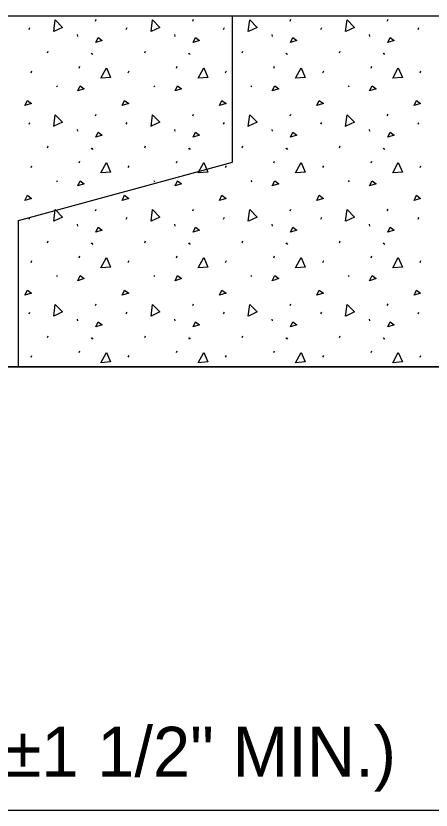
# Model space of a CAD drawing. Extents: x 49991.4 to 50021, y 49987.6 to 50011.4.
# Drawn here: x 50013.228 to 50013.726, y 49990.392 to 49991.345 of the extents above; entities that cross this region are included whole.
import ezdxf

# ---------------------------------------------------------------- set-up
doc = ezdxf.new("R2010")
doc.units = 0
for name, color, linetype in [('Level 1', 7, 'Continuous'), ('Level 2', 7, 'Continuous'), ('Level 3', 7, 'Continuous')]:
    doc.layers.add(name, color=color, linetype=linetype)

msp = doc.modelspace()

# ---------------------------------------------------------------- linework, layer by layer
at = {"layer": 'Level 1'}
for p, q in [((50012.2443, 49991.3452), (50014.4739, 49991.3452)), ((50012.2443, 49991.3452), (50014.4739, 49991.3452)), ((50013.4875, 49991.1697), (50013.4875, 49991.3452)), ((50013.3229, 49991.3389), (50013.3239, 49991.3411)), ((50013.4396, 49991.3389), (50013.4406, 49991.3411)), ((50013.5563, 49991.3389), (50013.5573, 49991.3411)), ((50013.673, 49991.3389), (50013.674, 49991.3411)), ((50013.2433, 49991.3289), (50013.2442, 49991.3311)), ((50013.3599, 49991.3289), (50013.3609, 49991.3311)), ((50013.4766, 49991.3289), (50013.4776, 49991.3311)), ((50013.5933, 49991.3289), (50013.5943, 49991.3311)), ((50013.71, 49991.3289), (50013.711, 49991.3311)), ((50013.3012, 49991.3228), (50013.3014, 49991.3206)), ((50013.4179, 49991.3228), (50013.4181, 49991.3206)), ((50013.5346, 49991.3228), (50013.5348, 49991.3206)), ((50013.6512, 49991.3228), (50013.6515, 49991.3206)), ((50013.2654, 49991.3007), (50013.2664, 49991.3029)), ((50013.3178, 49991.3007), (50013.3188, 49991.2992)), ((50013.3188, 49991.3001), (50013.3197, 49991.2987)), ((50013.3821, 49991.3007), (50013.3831, 49991.3029)), ((50013.4345, 49991.3007), (50013.4355, 49991.2992)), ((50013.4355, 49991.3001), (50013.4364, 49991.2987)), ((50013.4988, 49991.3007), (50013.4998, 49991.3029)), ((50013.5512, 49991.3007), (50013.5522, 49991.2992)), ((50013.5522, 49991.3001), (50013.5531, 49991.2987)), ((50013.6155, 49991.3007), (50013.6165, 49991.3029)), ((50013.6679, 49991.3007), (50013.6688, 49991.2992)), ((50013.6688, 49991.3001), (50013.6698, 49991.2987)), ((50013.2457, 49991.277), (50013.2467, 49991.2792)), ((50013.3034, 49991.2826), (50013.3044, 49991.2848)), ((50013.3624, 49991.277), (50013.3634, 49991.2792)), ((50013.4201, 49991.2826), (50013.4211, 49991.2848)), ((50013.4791, 49991.277), (50013.48, 49991.2792)), ((50013.5368, 49991.2826), (50013.5378, 49991.2848)), ((50013.5958, 49991.277), (50013.5967, 49991.2792)), ((50013.6535, 49991.2826), (50013.6545, 49991.2848)), ((50013.7124, 49991.277), (50013.7134, 49991.2792)), ((50013.2761, 49991.2614), (50013.2771, 49991.26)), ((50013.3928, 49991.2614), (50013.3938, 49991.26)), ((50013.5095, 49991.2614), (50013.5105, 49991.26)), ((50013.6262, 49991.2614), (50013.6272, 49991.26)), ((50013.3229, 49991.2251), (50013.3239, 49991.2273)), ((50013.4396, 49991.2251), (50013.4406, 49991.2273)), ((50013.5563, 49991.2251), (50013.5573, 49991.2273)), ((50013.673, 49991.2251), (50013.674, 49991.2273)), ((50013.2433, 49991.2152), (50013.2442, 49991.2173)), ((50013.3599, 49991.2152), (50013.3609, 49991.2173)), ((50013.4766, 49991.2152), (50013.4776, 49991.2173)), ((50013.5933, 49991.2152), (50013.5943, 49991.2173)), ((50013.71, 49991.2152), (50013.711, 49991.2173)), ((50013.3012, 49991.209), (50013.3014, 49991.2068)), ((50013.4179, 49991.209), (50013.4181, 49991.2068)), ((50013.5346, 49991.209), (50013.5348, 49991.2068)), ((50013.6512, 49991.209), (50013.6515, 49991.2068)), ((50013.2654, 49991.1869), (50013.2664, 49991.1891)), ((50013.3178, 49991.1869), (50013.3188, 49991.1854)), ((50013.3188, 49991.1863), (50013.3197, 49991.1849)), ((50013.3821, 49991.1869), (50013.3831, 49991.1891)), ((50013.4345, 49991.1869), (50013.4355, 49991.1854)), ((50013.4355, 49991.1863), (50013.4364, 49991.1849)), ((50013.4988, 49991.1869), (50013.4998, 49991.1891)), ((50013.5512, 49991.1869), (50013.5522, 49991.1854)), ((50013.5522, 49991.1863), (50013.5531, 49991.1849)), ((50013.6155, 49991.1869), (50013.6165, 49991.1891)), ((50013.6679, 49991.1869), (50013.6688, 49991.1854)), ((50013.6688, 49991.1863), (50013.6698, 49991.1849)), ((50013.2306, 49991.0998), (50013.4875, 49991.1697)), ((50013.2457, 49991.1632), (50013.2467, 49991.1654)), ((50013.3034, 49991.1688), (50013.3044, 49991.171)), ((50013.3624, 49991.1632), (50013.3634, 49991.1654)), ((50013.4201, 49991.1688), (50013.4211, 49991.171)), ((50013.4791, 49991.1632), (50013.48, 49991.1654)), ((50013.5368, 49991.1688), (50013.5378, 49991.171)), ((50013.5958, 49991.1632), (50013.5967, 49991.1654)), ((50013.6535, 49991.1688), (50013.6545, 49991.171)), ((50013.7124, 49991.1632), (50013.7134, 49991.1654)), ((50013.2761, 49991.1477), (50013.2771, 49991.1462)), ((50013.3928, 49991.1477), (50013.3938, 49991.1462)), ((50013.5095, 49991.1477), (50013.5105, 49991.1462)), ((50013.6262, 49991.1477), (50013.6272, 49991.1462)), ((50013.3229, 49991.1114), (50013.3239, 49991.1135)), ((50013.4396, 49991.1114), (50013.4406, 49991.1135)), ((50013.5563, 49991.1114), (50013.5573, 49991.1135)), ((50013.673, 49991.1114), (50013.674, 49991.1135)), ((50013.2306, 49990.9242), (50013.2306, 49991.0998)), ((50013.2433, 49991.1014), (50013.2442, 49991.1036)), ((50013.3599, 49991.1014), (50013.3609, 49991.1036)), ((50013.4766, 49991.1014), (50013.4776, 49991.1036)), ((50013.5933, 49991.1014), (50013.5943, 49991.1036)), ((50013.71, 49991.1014), (50013.711, 49991.1036)), ((50013.3012, 49991.0952), (50013.3014, 49991.0931)), ((50013.4179, 49991.0952), (50013.4181, 49991.0931)), ((50013.5346, 49991.0952), (50013.5348, 49991.0931)), ((50013.6512, 49991.0952), (50013.6515, 49991.0931)), ((50013.2654, 49991.0731), (50013.2664, 49991.0753)), ((50013.3178, 49991.0731), (50013.3188, 49991.0716)), ((50013.3188, 49991.0726), (50013.3197, 49991.0711)), ((50013.3821, 49991.0731), (50013.3831, 49991.0753)), ((50013.4345, 49991.0731), (50013.4355, 49991.0716)), ((50013.4355, 49991.0726), (50013.4364, 49991.0711)), ((50013.4988, 49991.0731), (50013.4998, 49991.0753)), ((50013.5512, 49991.0731), (50013.5522, 49991.0716)), ((50013.5522, 49991.0726), (50013.5531, 49991.0711)), ((50013.6155, 49991.0731), (50013.6165, 49991.0753)), ((50013.6679, 49991.0731), (50013.6688, 49991.0716)), ((50013.6688, 49991.0726), (50013.6698, 49991.0711)), ((50013.2457, 49991.0494), (50013.2467, 49991.0516)), ((50013.3034, 49991.0551), (50013.3044, 49991.0572)), ((50013.3624, 49991.0494), (50013.3634, 49991.0516)), ((50013.4201, 49991.0551), (50013.4211, 49991.0572)), ((50013.4791, 49991.0494), (50013.48, 49991.0516)), ((50013.5368, 49991.0551), (50013.5378, 49991.0572)), ((50013.5958, 49991.0494), (50013.5967, 49991.0516)), ((50013.6535, 49991.0551), (50013.6545, 49991.0572)), ((50013.7124, 49991.0494), (50013.7134, 49991.0516)), ((50013.2761, 49991.0339), (50013.2771, 49991.0324)), ((50013.3928, 49991.0339), (50013.3938, 49991.0324)), ((50013.5095, 49991.0339), (50013.5105, 49991.0324)), ((50013.6262, 49991.0339), (50013.6272, 49991.0324)), ((50013.3229, 49990.9976), (50013.3239, 49990.9998)), ((50013.4396, 49990.9976), (50013.4406, 49990.9998)), ((50013.5563, 49990.9976), (50013.5573, 49990.9998)), ((50013.673, 49990.9976), (50013.674, 49990.9998)), ((50013.2433, 49990.9876), (50013.2442, 49990.9898)), ((50013.3599, 49990.9876), (50013.3609, 49990.9898)), ((50013.4766, 49990.9876), (50013.4776, 49990.9898)), ((50013.5933, 49990.9876), (50013.5943, 49990.9898)), ((50013.71, 49990.9876), (50013.711, 49990.9898)), ((50013.3012, 49990.9815), (50013.3014, 49990.9793)), ((50013.4179, 49990.9815), (50013.4181, 49990.9793)), ((50013.5346, 49990.9815), (50013.5348, 49990.9793)), ((50013.6512, 49990.9815), (50013.6515, 49990.9793)), ((50013.2654, 49990.9593), (50013.2664, 49990.9615)), ((50013.3178, 49990.9593), (50013.3188, 49990.9579)), ((50013.3188, 49990.9588), (50013.3197, 49990.9573)), ((50013.3821, 49990.9593), (50013.3831, 49990.9615)), ((50013.4345, 49990.9593), (50013.4355, 49990.9579)), ((50013.4355, 49990.9588), (50013.4364, 49990.9573)), ((50013.4988, 49990.9593), (50013.4998, 49990.9615)), ((50013.5512, 49990.9593), (50013.5522, 49990.9579)), ((50013.5522, 49990.9588), (50013.5531, 49990.9573)), ((50013.6155, 49990.9593), (50013.6165, 49990.9615)), ((50013.6679, 49990.9593), (50013.6688, 49990.9579)), ((50013.6688, 49990.9588), (50013.6698, 49990.9573)), ((50013.2457, 49990.9357), (50013.2467, 49990.9378)), ((50013.3034, 49990.9413), (50013.3044, 49990.9435)), ((50013.3624, 49990.9357), (50013.3634, 49990.9378)), ((50013.4201, 49990.9413), (50013.4211, 49990.9435)), ((50013.4791, 49990.9357), (50013.48, 49990.9378)), ((50013.5368, 49990.9413), (50013.5378, 49990.9435)), ((50013.5958, 49990.9357), (50013.5967, 49990.9378)), ((50013.6535, 49990.9413), (50013.6545, 49990.9435)), ((50013.7124, 49990.9357), (50013.7134, 49990.9378)), ((50012.1908, 49990.9242), (50014.5274, 49990.9242)), ((50014.843, 49990.9242), (50012.1908, 49990.9242)), ((50014.5274, 49990.9242), (50012.1908, 49990.9242)), ((50012.1908, 49990.9242), (50014.843, 49990.9242))]:
    msp.add_line(p, q, dxfattribs=at)
for points in [[(50013.2729, 49991.3264), (50013.2748, 49991.3404), (50013.2835, 49991.3313), (50013.2731, 49991.3265)], [(50013.3896, 49991.3264), (50013.3915, 49991.3404), (50013.4002, 49991.3313), (50013.3898, 49991.3265)], [(50013.5063, 49991.3264), (50013.5082, 49991.3404), (50013.5169, 49991.3313), (50013.5065, 49991.3265)], [(50013.623, 49991.3264), (50013.6249, 49991.3404), (50013.6336, 49991.3313), (50013.6232, 49991.3265)], [(50013.3234, 49991.3134), (50013.3263, 49991.3194), (50013.3312, 49991.3158), (50013.3234, 49991.3134)], [(50013.4401, 49991.3134), (50013.443, 49991.3194), (50013.4479, 49991.3158), (50013.4401, 49991.3134)], [(50013.5568, 49991.3134), (50013.5597, 49991.3194), (50013.5646, 49991.3158), (50013.5568, 49991.3134)], [(50013.6735, 49991.3134), (50013.6764, 49991.3194), (50013.6813, 49991.3158), (50013.6735, 49991.3134)], [(50013.3295, 49991.2705), (50013.3361, 49991.2829), (50013.3412, 49991.2714), (50013.3297, 49991.2705)], [(50013.4462, 49991.2705), (50013.4528, 49991.2829), (50013.4579, 49991.2714), (50013.4464, 49991.2705)], [(50013.5629, 49991.2705), (50013.5695, 49991.2829), (50013.5746, 49991.2714), (50013.5631, 49991.2705)], [(50013.6796, 49991.2705), (50013.6861, 49991.2829), (50013.6913, 49991.2714), (50013.6798, 49991.2705)], [(50013.3017, 49991.2551), (50013.3046, 49991.2612), (50013.3095, 49991.2575), (50013.3017, 49991.2551)], [(50013.4184, 49991.2551), (50013.4213, 49991.2612), (50013.4262, 49991.2575), (50013.4184, 49991.2551)], [(50013.5351, 49991.2551), (50013.538, 49991.2612), (50013.5429, 49991.2575), (50013.5351, 49991.2551)], [(50013.6518, 49991.2551), (50013.6547, 49991.2612), (50013.6596, 49991.2575), (50013.6518, 49991.2551)], [(50013.2384, 49991.2377), (50013.2414, 49991.2438), (50013.2462, 49991.2401), (50013.2384, 49991.2377)], [(50013.3551, 49991.2377), (50013.358, 49991.2438), (50013.3629, 49991.2401), (50013.3551, 49991.2377)], [(50013.4718, 49991.2377), (50013.4747, 49991.2438), (50013.4796, 49991.2401), (50013.4718, 49991.2377)], [(50013.5885, 49991.2377), (50013.5914, 49991.2438), (50013.5963, 49991.2401), (50013.5885, 49991.2377)], [(50013.7052, 49991.2377), (50013.7081, 49991.2438), (50013.713, 49991.2401), (50013.7052, 49991.2377)], [(50013.2729, 49991.2126), (50013.2748, 49991.2266), (50013.2835, 49991.2176), (50013.2731, 49991.2127)], [(50013.3896, 49991.2126), (50013.3915, 49991.2266), (50013.4002, 49991.2176), (50013.3898, 49991.2127)], [(50013.5063, 49991.2126), (50013.5082, 49991.2266), (50013.5169, 49991.2176), (50013.5065, 49991.2127)], [(50013.623, 49991.2126), (50013.6249, 49991.2266), (50013.6336, 49991.2176), (50013.6232, 49991.2127)], [(50013.3234, 49991.1996), (50013.3263, 49991.2057), (50013.3312, 49991.202), (50013.3234, 49991.1996)], [(50013.4401, 49991.1996), (50013.443, 49991.2057), (50013.4479, 49991.202), (50013.4401, 49991.1996)], [(50013.5568, 49991.1996), (50013.5597, 49991.2057), (50013.5646, 49991.202), (50013.5568, 49991.1996)], [(50013.6735, 49991.1996), (50013.6764, 49991.2057), (50013.6813, 49991.202), (50013.6735, 49991.1996)], [(50013.3295, 49991.1567), (50013.3361, 49991.1691), (50013.3412, 49991.1576), (50013.3297, 49991.1567)], [(50013.4462, 49991.1567), (50013.4528, 49991.1691), (50013.4579, 49991.1576), (50013.4464, 49991.1567)], [(50013.5629, 49991.1567), (50013.5695, 49991.1691), (50013.5746, 49991.1576), (50013.5631, 49991.1567)], [(50013.6796, 49991.1567), (50013.6861, 49991.1691), (50013.6913, 49991.1576), (50013.6798, 49991.1567)], [(50013.3017, 49991.1413), (50013.3046, 49991.1474), (50013.3095, 49991.1438), (50013.3017, 49991.1413)], [(50013.4184, 49991.1413), (50013.4213, 49991.1474), (50013.4262, 49991.1438), (50013.4184, 49991.1413)], [(50013.5351, 49991.1413), (50013.538, 49991.1474), (50013.5429, 49991.1438), (50013.5351, 49991.1413)], [(50013.6518, 49991.1413), (50013.6547, 49991.1474), (50013.6596, 49991.1438), (50013.6518, 49991.1413)], [(50013.2384, 49991.1239), (50013.2414, 49991.13), (50013.2462, 49991.1263), (50013.2384, 49991.1239)], [(50013.3551, 49991.1239), (50013.358, 49991.13), (50013.3629, 49991.1263), (50013.3551, 49991.1239)], [(50013.4718, 49991.1239), (50013.4747, 49991.13), (50013.4796, 49991.1263), (50013.4718, 49991.1239)], [(50013.5885, 49991.1239), (50013.5914, 49991.13), (50013.5963, 49991.1263), (50013.5885, 49991.1239)], [(50013.7052, 49991.1239), (50013.7081, 49991.13), (50013.713, 49991.1263), (50013.7052, 49991.1239)], [(50013.2729, 49991.0988), (50013.2748, 49991.1128), (50013.2835, 49991.1038), (50013.2731, 49991.0989)], [(50013.3896, 49991.0988), (50013.3915, 49991.1128), (50013.4002, 49991.1038), (50013.3898, 49991.0989)], [(50013.5063, 49991.0988), (50013.5082, 49991.1128), (50013.5169, 49991.1038), (50013.5065, 49991.0989)], [(50013.623, 49991.0988), (50013.6249, 49991.1128), (50013.6336, 49991.1038), (50013.6232, 49991.0989)], [(50013.3234, 49991.0858), (50013.3263, 49991.0919), (50013.3312, 49991.0882), (50013.3234, 49991.0858)], [(50013.4401, 49991.0858), (50013.443, 49991.0919), (50013.4479, 49991.0882), (50013.4401, 49991.0858)], [(50013.5568, 49991.0858), (50013.5597, 49991.0919), (50013.5646, 49991.0882), (50013.5568, 49991.0858)], [(50013.6735, 49991.0858), (50013.6764, 49991.0919), (50013.6813, 49991.0882), (50013.6735, 49991.0858)], [(50013.3295, 49991.0429), (50013.3361, 49991.0553), (50013.3412, 49991.0438), (50013.3297, 49991.0429)], [(50013.4462, 49991.0429), (50013.4528, 49991.0553), (50013.4579, 49991.0438), (50013.4464, 49991.0429)], [(50013.5629, 49991.0429), (50013.5695, 49991.0553), (50013.5746, 49991.0438), (50013.5631, 49991.0429)], [(50013.6796, 49991.0429), (50013.6861, 49991.0553), (50013.6913, 49991.0438), (50013.6798, 49991.0429)], [(50013.3017, 49991.0275), (50013.3046, 49991.0336), (50013.3095, 49991.03), (50013.3017, 49991.0275)], [(50013.4184, 49991.0275), (50013.4213, 49991.0336), (50013.4262, 49991.03), (50013.4184, 49991.0275)], [(50013.5351, 49991.0275), (50013.538, 49991.0336), (50013.5429, 49991.03), (50013.5351, 49991.0275)], [(50013.6518, 49991.0275), (50013.6547, 49991.0336), (50013.6596, 49991.03), (50013.6518, 49991.0275)], [(50013.2384, 49991.0101), (50013.2414, 49991.0162), (50013.2462, 49991.0125), (50013.2384, 49991.0101)], [(50013.3551, 49991.0101), (50013.358, 49991.0162), (50013.3629, 49991.0125), (50013.3551, 49991.0101)], [(50013.4718, 49991.0101), (50013.4747, 49991.0162), (50013.4796, 49991.0125), (50013.4718, 49991.0101)], [(50013.5885, 49991.0101), (50013.5914, 49991.0162), (50013.5963, 49991.0125), (50013.5885, 49991.0101)], [(50013.7052, 49991.0101), (50013.7081, 49991.0162), (50013.713, 49991.0125), (50013.7052, 49991.0101)], [(50013.2729, 49990.9851), (50013.2748, 49990.999), (50013.2835, 49990.99), (50013.2731, 49990.9851)], [(50013.3896, 49990.9851), (50013.3915, 49990.999), (50013.4002, 49990.99), (50013.3898, 49990.9851)], [(50013.5063, 49990.9851), (50013.5082, 49990.999), (50013.5169, 49990.99), (50013.5065, 49990.9851)], [(50013.623, 49990.9851), (50013.6249, 49990.999), (50013.6336, 49990.99), (50013.6232, 49990.9851)], [(50013.3234, 49990.972), (50013.3263, 49990.9781), (50013.3312, 49990.9744), (50013.3234, 49990.972)], [(50013.4401, 49990.972), (50013.443, 49990.9781), (50013.4479, 49990.9744), (50013.4401, 49990.972)], [(50013.5568, 49990.972), (50013.5597, 49990.9781), (50013.5646, 49990.9744), (50013.5568, 49990.972)], [(50013.6735, 49990.972), (50013.6764, 49990.9781), (50013.6813, 49990.9744), (50013.6735, 49990.972)], [(50013.3295, 49990.9291), (50013.3361, 49990.9415), (50013.3412, 49990.9301), (50013.3297, 49990.9291)], [(50013.4462, 49990.9291), (50013.4528, 49990.9415), (50013.4579, 49990.9301), (50013.4464, 49990.9291)], [(50013.5629, 49990.9291), (50013.5695, 49990.9415), (50013.5746, 49990.9301), (50013.5631, 49990.9291)], [(50013.6796, 49990.9291), (50013.6861, 49990.9415), (50013.6913, 49990.9301), (50013.6798, 49990.9291)]]:
    msp.add_lwpolyline(points, dxfattribs=at)
at = {"layer": 'Level 3'}
msp.add_line((50012.2174, 49990.3923), (50014.5005, 49990.3923), dxfattribs=at)

# ---------------------------------------------------------------- texts
at = {"layer": 'Level 2'}
msp.add_text('32" (ADJ. ±1 1/2" MIN.)', height=0.06, dxfattribs=at).set_placement((50012.85119, 49990.4323))

doc.saveas('drawing.dxf')
